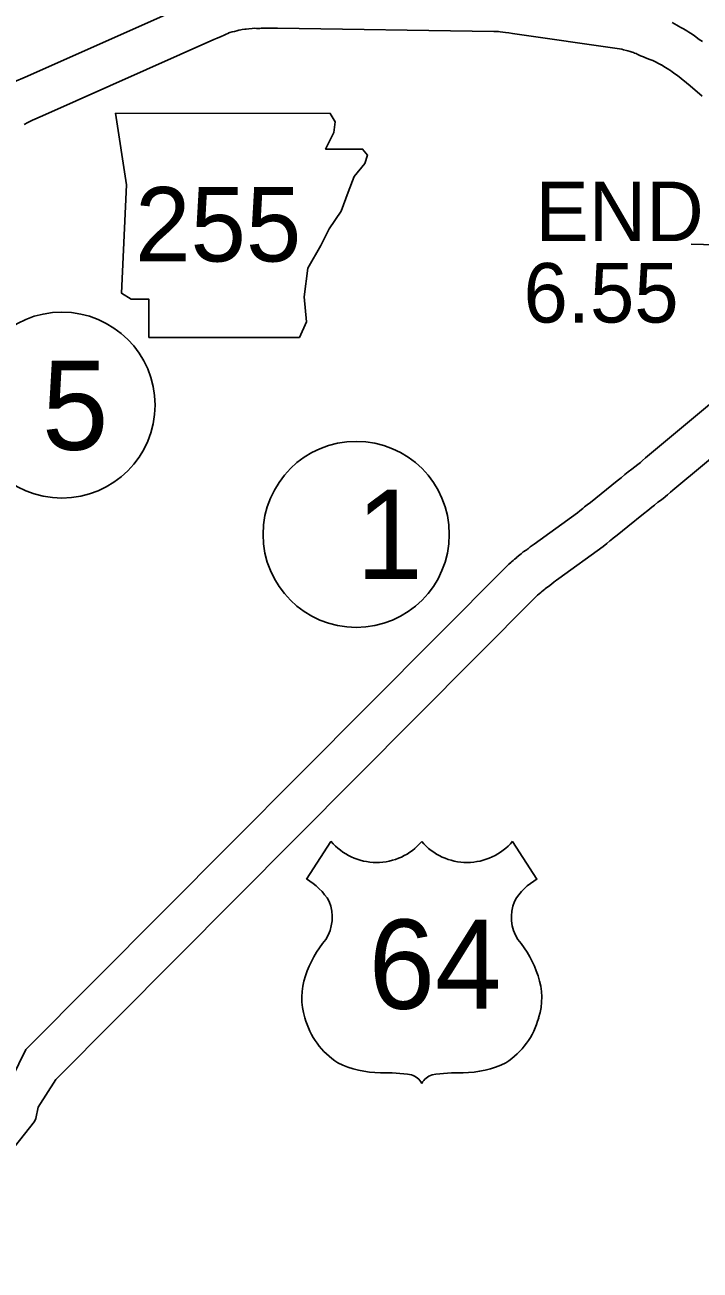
# Model space of a CAD drawing. Extents: x -939622 to -934245, y 1383184 to 1385301.
# Drawn here: x -936437.59 to -936423.23, y 1384585.59 to 1384612.1 of the extents above; entities that cross this region are included whole.
import ezdxf

# ---------------------------------------------------------------- set-up
doc = ezdxf.new("R2010")
doc.units = 0
for name, color, linetype in [('Level 10', 7, 'Continuous'), ('Level 15', 7, 'Continuous'), ('Level 21', 7, 'Continuous'), ('Level 22', 7, 'Continuous'), ('Level 25', 7, 'Continuous'), ('Level 27', 7, 'Continuous')]:
    doc.layers.add(name, color=color, linetype=linetype)

msp = doc.modelspace()

# ---------------------------------------------------------------- linework, layer by layer
at = {"layer": 'Level 10'}
for points in [[(-936433.901, 1384612.629), (-936437.584, 1384610.987), (-936437.819, 1384610.884)], [(-936423.185, 1384610.584), (-936423.446, 1384610.799), (-936423.714, 1384611.018), (-936423.772, 1384611.056), (-936423.826, 1384611.098), (-936423.861, 1384611.125), (-936423.878, 1384611.138), (-936423.895, 1384611.148), (-936423.934, 1384611.17), (-936424.004, 1384611.214), (-936424.05, 1384611.245), (-936424.06, 1384611.25), (-936424.24, 1384611.344), (-936424.324, 1384611.368), (-936424.408, 1384611.404), (-936424.437, 1384611.419), (-936424.502, 1384611.44), (-936424.568, 1384611.477), (-936424.592, 1384611.487), (-936424.624, 1384611.5), (-936424.645, 1384611.509), (-936424.679, 1384611.52), (-936424.72, 1384611.53), (-936424.772, 1384611.546), (-936424.798, 1384611.553), (-936424.859, 1384611.567), (-936424.896, 1384611.579), (-936427.225, 1384611.918), (-936427.299, 1384611.927), (-936427.369, 1384611.938), (-936427.424, 1384611.945), (-936427.482, 1384611.952), (-936427.518, 1384611.955), (-936427.579, 1384611.96), (-936427.596, 1384611.961), (-936427.619, 1384611.961), (-936432.22, 1384612.027), (-936432.57, 1384612.027), (-936432.595, 1384612.024), (-936432.67, 1384612.024), (-936432.717, 1384612.026), (-936432.761, 1384612.019), (-936432.832, 1384612.014), (-936432.886, 1384612.009), (-936432.916, 1384612.005), (-936432.969, 1384611.997), (-936432.999, 1384611.992), (-936433.043, 1384611.983), (-936433.084, 1384611.975), (-936433.136, 1384611.961), (-936433.183, 1384611.95), (-936433.234, 1384611.934), (-936433.253, 1384611.929), (-936433.263, 1384611.924), (-936433.323, 1384611.897), (-936433.357, 1384611.881), (-936433.42, 1384611.85), (-936433.502, 1384611.815), (-936433.571, 1384611.791), (-936437.221, 1384610.163), (-936437.434, 1384610.07), (-936437.489, 1384610.042), (-936437.542, 1384610.011), (-936437.592, 1384609.988), (-936437.61, 1384609.978)], [(-936423.18, 1384611.744), (-936423.248, 1384611.789), (-936423.278, 1384611.812), (-936423.321, 1384611.845), (-936423.376, 1384611.886), (-936423.438, 1384611.923), (-936423.471, 1384611.942), (-936423.515, 1384611.969), (-936423.584, 1384612.016), (-936423.64, 1384612.046), (-936423.692, 1384612.073), (-936423.726, 1384612.091), (-936423.827, 1384612.147)]]:
    msp.add_lwpolyline(points, dxfattribs=at)
at = {"layer": 'Level 15'}
for points in [[(-936421.618, 1384605.194), (-936424.391, 1384602.88), (-936424.457, 1384602.822), (-936424.502, 1384602.782), (-936424.557, 1384602.739), (-936424.623, 1384602.691), (-936424.685, 1384602.642), (-936424.758, 1384602.585), (-936424.833, 1384602.526), (-936424.913, 1384602.457), (-936424.995, 1384602.393), (-936425.336, 1384602.119), (-936425.566, 1384601.931), (-936425.63, 1384601.88), (-936425.687, 1384601.836), (-936425.729, 1384601.802), (-936425.786, 1384601.753), (-936425.836, 1384601.714), (-936426.759, 1384601.047), (-936426.848, 1384600.984), (-936426.88, 1384600.954), (-936426.893, 1384600.945), (-936426.913, 1384600.929), (-936426.929, 1384600.917), (-936426.994, 1384600.878), (-936427.035, 1384600.835), (-936427.064, 1384600.817), (-936427.126, 1384600.766), (-936427.145, 1384600.748), (-936427.178, 1384600.723), (-936427.206, 1384600.699), (-936427.242, 1384600.669), (-936427.259, 1384600.653), (-936427.303, 1384600.621), (-936427.359, 1384600.563), (-936437.573, 1384590.285)], [(-936421.12, 1384604.437), (-936423.808, 1384602.194), (-936423.861, 1384602.148), (-936423.924, 1384602.092), (-936424.017, 1384602.019), (-936424.076, 1384601.976), (-936424.128, 1384601.935), (-936424.204, 1384601.876), (-936424.26, 1384601.832), (-936424.341, 1384601.762), (-936424.437, 1384601.687), (-936424.769, 1384601.42), (-936424.998, 1384601.233), (-936425.077, 1384601.169), (-936425.132, 1384601.127), (-936425.15, 1384601.113), (-936425.213, 1384601.059), (-936425.294, 1384600.995), (-936426.235, 1384600.315), (-936426.284, 1384600.28), (-936426.304, 1384600.262), (-936426.34, 1384600.234), (-936426.428, 1384600.164), (-936426.519, 1384600.097), (-936426.532, 1384600.089), (-936426.536, 1384600.086), (-936426.569, 1384600.055), (-936426.608, 1384600.026), (-936426.622, 1384600.014), (-936426.652, 1384599.989), (-936426.688, 1384599.956), (-936426.71, 1384599.94), (-936426.719, 1384599.931), (-936436.935, 1384589.651)], [(-936437.573, 1384590.285), (-936438.016, 1384589.372)], [(-936436.935, 1384589.651), (-936437.311, 1384589.06)], [(-936437.311, 1384589.06), (-936437.361, 1384588.818), (-936437.391, 1384588.757), (-936441.273, 1384583.839)]]:
    msp.add_lwpolyline(points, dxfattribs=at)
at = {"layer": 'Level 21'}
msp.add_lwpolyline([(-936435.663, 1384610.216), (-936435.435, 1384608.693), (-936435.536, 1384606.384), (-936435.333, 1384606.257), (-936434.953, 1384606.257), (-936434.953, 1384605.445), (-936431.755, 1384605.445), (-936431.603, 1384605.775), (-936431.654, 1384606.308), (-936431.578, 1384606.917), (-936431.299, 1384607.399), (-936431.121, 1384607.754), (-936430.867, 1384608.135), (-936430.715, 1384608.541), (-936430.588, 1384608.871), (-936430.36, 1384609.15), (-936430.309, 1384609.328), (-936430.41, 1384609.454), (-936431.197, 1384609.454), (-936431.019, 1384609.81), (-936430.994, 1384610.038), (-936431.099, 1384610.214)], close=True, dxfattribs=at)
at = {"layer": 'Level 22'}
for p, q in [((-936431.082, 1384594.718), (-936431.601, 1384593.915)), ((-936427.221, 1384594.718), (-936426.702, 1384593.915))]:
    msp.add_line(p, q, dxfattribs=at)
for centre, radius, start, end in [((-936430.115, 1384595.532), 1.264, 220.075, 319.6701), ((-936428.188, 1384595.532), 1.264, 220.3299, 319.925), ((-936432.279, 1384592.75), 1.349, 30.7809, 59.9883), ((-936426.023, 1384592.75), 1.349, 120.0117, 149.2191), ((-936431.982, 1384593.105), 0.925, 328.8105, 21.2108), ((-936426.32, 1384593.105), 0.925, 158.7892, 211.1895), ((-936429.564, 1384591.21), 2.157, 138.9565, 162.6913), ((-936428.738, 1384591.21), 2.157, 17.3087, 41.0435), ((-936430.276, 1384591.387), 1.426, 160.9576, 197.3819), ((-936428.026, 1384591.387), 1.426, 342.6181, 19.0424), ((-936430.044, 1384591.391), 1.65, 195.1074, 237.1312), ((-936428.258, 1384591.391), 1.65, 302.8688, 344.8926), ((-936430.014, 1384591.91), 2.118, 244.0771, 269.5779), ((-936428.289, 1384591.91), 2.118, 270.4221, 295.9229), ((-936429.965, 1384585.913), 3.88, 81.1942, 90.9539), ((-936429.479, 1384589.391), 0.372, 28.0342, 72.9864), ((-936428.823, 1384589.391), 0.372, 107.0136, 151.9658), ((-936428.338, 1384585.913), 3.88, 89.0461, 98.8058)]:
    msp.add_arc(centre, radius, start, end, dxfattribs=at)
at = {"layer": 'Level 25'}
msp.add_line((-936423.423, 1384607.432), (-936418.771, 1384607.315), dxfattribs=at)
at = {"layer": 'Level 27'}
for centre in [(-936436.805, 1384604.004), (-936430.546, 1384601.252)]:
    msp.add_ellipse(centre, major_axis=(0, 1.98), ratio=0.999998, dxfattribs=at)

# ---------------------------------------------------------------- texts
at = {"layer": 'Level 21'}
msp.add_text('255', height=1.584, dxfattribs=at).set_placement((-936435.248, 1384607.062))
at = {"layer": 'Level 22'}
msp.add_text('64', height=1.9008, dxfattribs=at).set_placement((-936430.282, 1384591.153))
at = {"layer": 'Level 25'}
for s, p in [('END', (-936426.732, 1384607.495)), ('6.55', (-936426.987, 1384605.762))]:
    msp.add_text(s, height=1.2672, dxfattribs=at).set_placement(p)
at = {"layer": 'Level 27'}
for s, p in [('5', (-936437.23, 1384603.053)), ('1', (-936430.546, 1384600.302))]:
    msp.add_text(s, height=1.901, dxfattribs=at).set_placement(p)

doc.saveas('drawing.dxf')
